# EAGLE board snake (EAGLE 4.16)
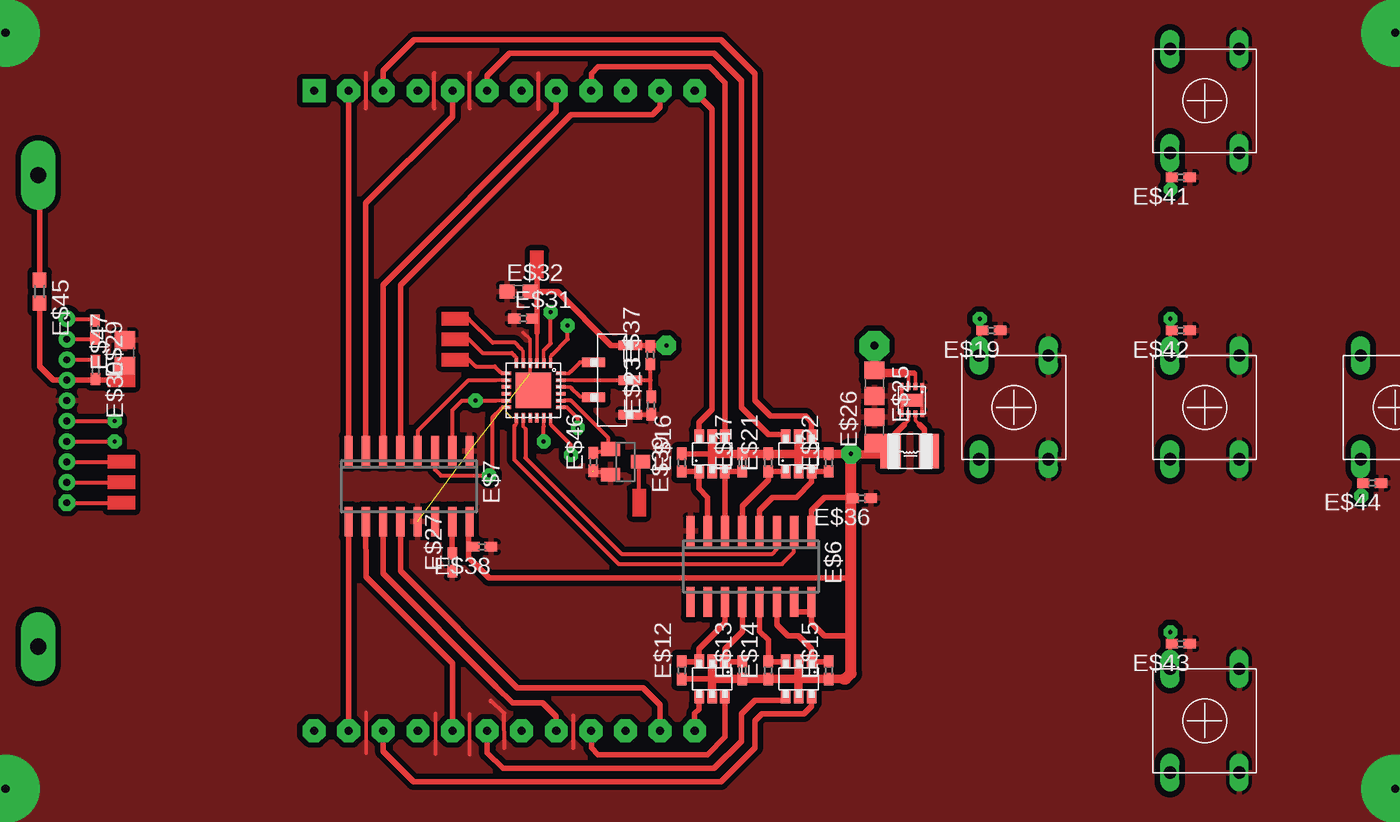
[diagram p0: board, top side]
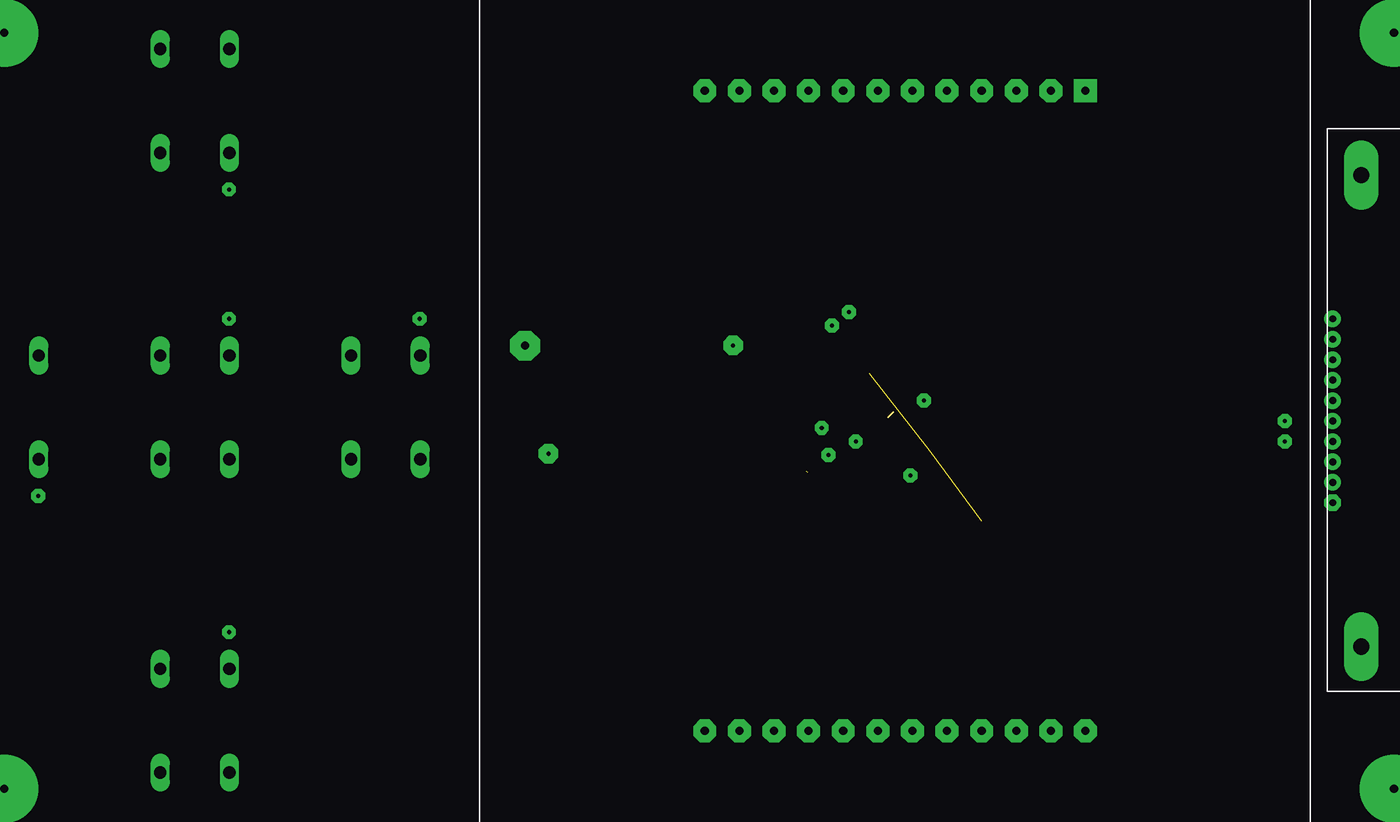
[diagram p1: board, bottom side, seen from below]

Size 0.4 x 0.4 mm. Coordinates in mm from the lower left corner, seen from the top.
Outline: 0.4,0 0,0.4
Copper layers (1*16): Top 0.035mm / dielectric 1.5mm / Bottom 0.035mm
Design rules "default": minimum track width 10mil, minimum drill 24mil, track to track 8mil, track to pad 8mil, pad to pad 8mil, via to via 8mil, smd to smd 8mil, copper to edge 40mil, drill to drill 8mil, minimum pad ring 10mil, minimum via ring 8mil, stop-mask expansion 4mil, vias tented up to drill 0mil, thermal gap 10mil

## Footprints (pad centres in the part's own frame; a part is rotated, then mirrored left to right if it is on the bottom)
LC2088AURYG1C = drill 0.6 pad 1.676 square: P$1 -13.97,-23.495 | drill 0.6 pad 1.676 octagon: P$2 -11.43,-23.495; P$3 -8.89,-23.495; P$4 -6.35,-23.495; P$5 -3.81,-23.495; P$6 -1.27,-23.495; P$7 1.27,-23.495; P$8 3.81,-23.495; P$9 6.35,-23.495; P$10 8.89,-23.495; P$11 11.43,-23.495; P$12 13.97,-23.495; P$13 -13.97,23.495; P$14 -11.43,23.495; P$15 -8.89,23.495; P$16 -6.35,23.495; P$17 -3.81,23.495; P$18 -1.27,23.495; P$19 1.27,23.495; P$20 3.81,23.495; P$21 6.35,23.495; P$22 8.89,23.495; P$23 11.43,23.495; P$24 13.97,23.495
SUPERSOT-6 = smd 0.7 x 1: P$1 -0.95,1.3; P$2 0,1.3; P$3 0.95,1.3; P$4 -0.95,-1.3; P$5 0,-1.3; P$6 0.95,-1.3
SO16 = smd 0.6 x 2.2: 1 -4.445,-2.6; 2 -3.175,-2.6; 3 -1.905,-2.6; 4 -0.635,-2.6; 5 0.635,-2.6; 6 1.905,-2.6; 7 3.175,-2.6; 8 4.445,-2.6; 9 4.445,2.6; 10 3.175,2.6; 11 1.905,2.6; 12 0.635,2.6; 13 -0.635,2.6; 14 -1.905,2.6; 15 -3.175,2.6; 16 -4.445,2.6
SW_TACT_KSL4 = drill 0.9 long: 1 -3.81,2.54; 2 -3.81,-2.54; 3 3.81,-2.54; 4 3.81,2.54
R0402 = smd 0.9 x 0.7: 1 -0.65,0; 2 0.65,0
C0402 = smd 0.9 x 0.7: 1 -0.65,0; 2 0.65,0
QFN24 = smd 0.7 x 0.25: 1 -2,1.25; 2 -2,0.75; 3 -2,0.25; 4 -2,-0.25; 5 -2,-0.75; 6 -2,-1.25; 13 2,-1.25; 14 2,-0.75; 15 2,-0.25; 16 2,0.25; 17 2,0.75; 18 2,1.25 | smd 0.25 x 0.7: 7 -1.25,-2; 8 -0.75,-2; 9 -0.25,-2; 10 0.25,-2; 11 0.75,-2; 12 1.25,-2; 19 1.25,2; 20 0.75,2; 21 0.25,2; 22 -0.25,2; 23 -0.75,2; 24 -1.25,2 | smd 2.6 x 2.6: EP 0,0
WSON8 = smd 0.28 x 0.5: 1 -1,-1; 2 -0.5,-1; 3 0,-1; 4 0.5,-1; 5 0.5,1; 6 0,1; 7 -0.5,1; 8 -1,1 | smd 1.6 x 0.9: EP -0.25,0
C0805 = smd 1.3 x 1.5: 1 -0.95,0; 2 0.95,0
LQH32C = smd 1.5 x 2.5: P$1 -1.4,0; P$2 1.4,0
C0603 = smd 1.1 x 1: 1 -0.85,0; 2 0.85,0
HEADER5S = smd 0.7 x 1.7: P$1 0,1.35; P$2 2.55,1.35; P$3 -2.55,1.35; P$4 -1.3,-1.35; P$5 1.25,-1.35
SOT23 = smd 1 x 1.4: 1 -0.95,-1.1; 2 0.95,-1.1; 3 0,1.1
R0603 = smd 1.1 x 1: 1 -0.85,0; 2 0.85,0
NHD-C0216-SPI = drill 0.5 pad 1.2 round: 1 0,0; 5 1.5,0; 6 3,0; 7 4.5,0; 8 6,0; 9 7.5,0; 10 9,0; 11 10.5,0; 12 12,0 | drill 0.5 pad 1.2 octagon: 13 13.5,0 | drill 1.2 pad 2.54 long: 18 24.05,2.1; 19 -10.55,2.1

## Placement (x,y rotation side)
E$1  [LC2088AURYG1C]  -0.14,0.5 180 bottom
E$2  [SUPERSOT-6]  not placed on the board
E$3  [SUPERSOT-6]  not placed on the board
E$4  [SUPERSOT-6]  not placed on the board
E$5  [SUPERSOT-6]  not placed on the board
E$6  [SO16]  not placed on the board
E$7  [SO16]  -7.13,-5.04 180 top
E$9  [SW_TACT_KSL4]  not placed on the board
E$10  [SW_TACT_KSL4]  not placed on the board
E$11  [SW_TACT_KSL4]  not placed on the board
E$12  [R0402]  not placed on the board
E$13  [R0402]  not placed on the board
E$14  [R0402]  not placed on the board
E$15  [R0402]  not placed on the board
E$16  [R0402]  not placed on the board
E$17  [R0402]  not placed on the board
E$18  [SW_TACT_KSL4]  not placed on the board
E$19  [C0402]  not placed on the board
E$20  [QFN24]  2,2 270 top
E$21  [R0402]  not placed on the board
E$22  [R0402]  not placed on the board
E$23  [R0402]  not placed on the board
E$24  [WSON8]  29.52,1.28 180 top  (outside the outline)
E$25  [C0805]  not placed on the board
E$26  [C0805]  not placed on the board
E$27  [C0402]  not placed on the board
E$28  [LQH32C]  not placed on the board
E$29  [R0402]  not placed on the board
E$30  [R0402]  not placed on the board
E$31  [R0402]  not placed on the board
E$32  [C0603]  not placed on the board
E$35  [HEADER5S]  not placed on the board
E$36  [R0402]  not placed on the board
E$37  [R0402]  not placed on the board
E$38  10K  [C0402]  not placed on the board
E$39  [SOT23]  not placed on the board
E$40  [SW_TACT_KSL4]  not placed on the board
E$41  [C0402]  not placed on the board
E$42  [C0402]  not placed on the board
E$43  [C0402]  not placed on the board
E$44  [C0402]  not placed on the board
E$45  [R0603]  not placed on the board
E$46  [R0402]  not placed on the board
E$47  [C0805]  not placed on the board
E$48  [NHD-C0216-SPI]  not placed on the board

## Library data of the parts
E$1 = display-hp
E$2-E$5 E$9-E$11 E$18 E$28 E$35 E$40 = sb
E$6 E$7 E$12-E$17 E$19 E$21-E$23 E$25 E$26 E$29-E$32 E$36 E$37 E$39 E$41-E$47 = ref-packages
E$20 = freescale
E$24 = texas
E$27 E$38 = rcl
E$48 = display-lcd

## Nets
GND: E$6.8 E$7.1 E$7.13 E$9.2 E$9.3 E$10.2 E$10.3 E$11.2 E$11.3 E$18.2 E$18.3 E$19.1 E$23.1 E$24.1 E$24.4 E$24.5 E$24.8 E$24.EP E$25.2 E$26.2 E$27.1 E$31.1 E$32.1 E$35.P$2 E$36.1 E$38.1 E$39.2 E$40.2 E$40.3 E$41.1 E$42.1 E$43.1 E$44.1 E$46.1 E$47.2 E$48.8
S$2: E$24.2 E$24.3
S$3: E$24.7
S$20: E$24.6

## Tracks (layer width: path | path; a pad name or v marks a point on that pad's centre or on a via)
GND  (via drill 0.6 pad 5)  (3 unrouted)
  Top 0.254: 29.02,1.28 E$24.4 | E$24.5 29.02,1.28 | 30.52,1.28 E$24.1 | 29.02,1.28 30.52,1.28 | 30.52,1.28 E$24.8 | -2.7,-24.75 -2.7,-21.75 | -5.2,-24.7 -5.2,-21.7 | -10.3,-24.65 -10.3,-21.65 | 1.25,6.25 1.75,5.75 1.75,3.25
  Top 0.305: 2.36,22.66 2.36,25.27 | -2.69,22.71 -2.69,25.31 | -5.29,22.71 -5.29,25.31 | 4.93,-24.27 4.93,-21.88 | -1.14,-20.84 -1.14,-20.76 -0.15,-21.7 -0.14,-24.27 | -10.29,22.71 -10.29,25.31 | 10.75,0.2 9.75,0.2 | 6.3,-4 7.3,-4
  other vias: -36.75,28.25 65.25,28.25 -36.75,-27.25 65.25,-27.25
  pour Top (isolate 0.406): 69.75,-30.93 -56.6,-30.93 -56.6,31.93 69.75,31.93
S$1
  Top 0.406: -9.05,24.05 -9.05,25.45 -6.75,27.75 15.75,27.75 18.25,25.25 18.25,1.25 19.4,0.1 22,0.1 22.4,-0.35 22.4,-1.3
S$2
  Top 0.254: E$24.3 29.52,3.28 | E$24.2 30.02,3.28 29.92,3.28
  Top 0.406: 29.52,3.28 29.92,3.28
S$3
  Top 0.254: E$24.7 30.02,-0.22 30.32,-0.52
  Top 0.406: 30.32,-0.52 30.67,-0.87 30.67,-1.72
S$4
  Top 0.406: 16.05,-1.25 16.05,24.6 14.9,25.75 6.75,25.75 6.25,25.25 6.25,24.05
S$5
  Top 0.406: 16.05,-14.74 16.05,-15.06 14.15,-16.96 14.15,-17.91 13.67,-17.91 12.88,-17.91
S$6
  Top 0.406: -10.31,-7.58 -10.3,-11.7 -3.95,-18.04 -3.95,-22.99
S$7
  Top 0.406: 17.32,-13.47 17.32,-15.69 16.05,-16.96 16.05,-17.91 17.32,-17.91
S$8
  Top 0.406: 18.59,-13.47 18.59,-15.69 19.23,-16.33 19.23,-17.91 20.5,-17.91
S$9
  Top 0.406: 19.86,-13.47 19.86,-15.22 20.66,-16.01 21.45,-16.01 22.4,-16.96 22.4,-17.91 23.67,-17.91
S$10
  Top 0.406: 14.78,-7.12 14.78,-5.85 14.15,-5.21 14.15,-3.95 12.88,-3.95
S$11
  Top 0.406: 16.05,-7.12 16.05,-3.95 17.32,-3.95
S$12
  Top 0.406: 17.32,-7.12 17.32,-6.48 19.23,-4.58 19.23,-3.95 20.18,-3.95 20.5,-3.95
S$13
  Top 0.406: 18.59,-7.75 18.59,-6.8 19.55,-5.85 21.29,-5.85 22.4,-4.74 22.4,-3.95 | 22.4,-3.95 22.56,-3.95 | 22.4,-3.95 23.67,-3.95
S$14
  Top 0.406: 12.88,-19.19 15.1,-19.19
  Top 0.61: 15.1,-20.45 15.1,-19.19 15.1,-17.91
S$15
  Top 0.61: 21.45,-20.45 21.45,-17.91
S$16
  Top 0.305: -32.1,-6.25 -28.75,-6.25
S$17
  Top 0.406: 21.25,-14.25 22.25,-14.25
S$18
  Top 0.406: 12.88,-2.68 15.1,-2.68
  Top 0.61: 15.1,-3.95 15.1,-2.68 15.1,-1.41
S$19
  Top 0.61: 21.45,-3.95 21.45,-1.41
S$20
  Top 0.254: E$24.6 29.52,-0.22 29.22,-0.52
  Top 0.406: 28.52,-1.22 29.22,-0.52
S$21
  Top 0.254: 1.4,-0.8 1.25,-0.65 1.25,-0.25
  Top 0.305: 19.85,-8.65 19.85,-9.65 19.55,-10 8.45,-10 1.4,-2.95 1.4,-0.8
S$22
  Top 0.254: 0.65,-0.55 0.75,-0.45 0.75,-0.25
  Top 0.305: 21.1,-8.35 21.1,-9.85 20.25,-10.75 8.25,-10.75 0.6,-3.1 0.6,-0.6 0.65,-0.55
S$23
  Top 0.406: 20.25,-1.25 19.25,-1.25 17.25,0.75 17.25,24.75 15.25,26.75 0.25,26.75 -1.4,25.1 -1.4,24.1
S$24
  Top 0.406: 6.25,-23 6.25,-24.25 6.75,-24.75 14.75,-24.75 16.05,-23.45 16.05,-20.9
S$25
  Top 0.406: 14.15,-1.25 14.15,-0.35 15.1,0.6 15.1,22.65 13.75,24
S$26
  Top 0.406: -9.05,-23 -9.05,-24.5 -6.8,-26.75 15.75,-26.75 18.25,-24.25 18.25,-22.25 18.75,-21.75 21.85,-21.75 22.4,-21.2 22.4,-20.2
S$27  (via drill 0.6 pad 2.18)
  Top 0.61: v27.02,5.28 27.02,3.28 29.27,3.28
S$28
  Top 0.61: 25.52,-2.72 28.12,-2.72
S$29
  Top 0.406: -1.4,-23.1 -1.4,-24.6 -0.25,-25.75 15.25,-25.75 17.25,-23.75 17.25,-21.75 18.25,-20.75 20.25,-20.75
S$30
  Top 0.406: 13.83,-22.99 13.83,-21.73 14.15,-21.41 14.15,-20.45
S$31
  Top 0.406: -2.75,-8.25 -2.75,-10.25 -1.25,-11.75 25.25,-11.75
S$32
  Top 0.254: -0.75,1.25 -0.25,1.25
  Top 0.305: -0.75,1.25 -3.25,1.25 -3.95,0.55 -3.95,-1.95
S$33
  Top 0.254: 4.7,3.35 4.6,3.25 4.3,3.25
  Top 0.305: 4.7,3.35 5.4,4.05 6.55,4.05
S$34
  Top 0.254: -0.75,2.75 0.15,2.75
  Top 0.305: -0.75,2.75 -2.75,2.75 -6.5,-1 -6.5,-2
S$35
  Top 0.305: -31.75,4.25 -30.25,4.25
S$36
  Top 0.305: -31.75,5.75 -30.25,5.75
S$37
  Top 0.305: -31.75,7.25 -30.25,7.25
S$38
  Top 0.305: 4.25,1.25 4.75,1.25 7.45,-1.45 7.45,-2.45
S$39
  Top 0.305: 9.75,-5.75 9.75,-3.25
S$40  (via drill 0.3 pad 1.02)
  Top 0.305: 4.25,0.75 4.45,0.75 5.25,-0.05 v5.25,-0.75
S$41  (via drill 0.3 pad 1.42)
  Top 0.254: 2.25,4.25 2.25,6.25
  Top 0.406: 2.25,6.25 2.25,9.25 | 2.25,9.25 3.75,9.25 7.7,5.3 v11.75,5.3 | 2.25,9.25 2.25,11.25
S$42
  Top 0.406: -28.75,2.75 -33.25,2.75 -34.25,3.75 -34.25,8.25
S$43
  Top 0.305: 34.75,4.75 34.75,7.2
S$44
  Top 0.406: 25.3,-5.85 23.36,-5.85 22.4,-6.8 22.4,-7.75
S$45
  Top 0.406: 25.3,-16.01 23.36,-16.01 22.4,-15.06 22.4,-14.11
S$46  (via drill 0.3 pad 1.02)
  other vias: -2.25,1.25
S$47
  Top 0.406: -34.25,10.25 -34.25,17.85
S$48
  Top 0.254: 0.75,4.3 0.75,4.4 0.6,4.55
  Top 0.305: 0.6,4.55 0.4,4.75 -1.75,4.75 -2.75,5.75 -3.25,5.75
S$49
  Top 0.254: 1.25,4.25 1.25,4.9 1.1,5.05
  Top 0.305: -3.25,7.25 -2.75,7.25 -1,5.5 0.65,5.5 1.1,5.05
S$51  (via drill 0.3 pad 1.02)
  Top 0.305: -32.1,-1.75 v-28.75,-1.75
S$52  (via drill 0.3 pad 1.02)
  Top 0.305: -32.15,-0.25 v-28.75,-0.25
S$53
  Top 0.254: 5,2.75 4.3,2.75
  Top 0.305: 5,2.75 10.6,2.75
S$54
  Top 0.254: 4.8,2.15 4.7,2.25 4.3,2.25
  Top 0.305: 4.8,2.15 5.4,1.55 5.95,1.55
S$55
  Top 0.305: 10.6,1.75 10.6,3.75
S$56  (via drill 0.3 pad 1.02)
  Top 0.254: 3.35,-0.6 3.25,-0.5 3.25,-0.25
  Top 0.305: 3.35,-0.6 4.75,-2 v4.75,-2.75
S$57
  Top 0.254: 2.75,4.25 2.75,4.95 2.85,5.05
  Top 0.305: 2.85,5.05 3.25,5.45 3.25,7.75
S$58
  Top 0.254: 3.35,4.6 3.25,4.5 3.25,4.25
  Top 0.305: 4.5,6.75 4.5,5.75 3.35,4.6
S$59  (via drill 0.3 pad 1.02)
  other vias: 4.5,6.75
S$60  (via drill 0.3 pad 1.02)
  other vias: 3.25,7.75
S$61
  Top 0.61: 15.1,-19.19 24.76,-19.19 | 25.3,-2.68 | 25.3,-2.68 24.76,-2.68 15.1,-2.68
  Top 0.813: 24.76,-19.19 24.89,-19.19 25.3,-18.78 25.3,-2.68
S$62  (via drill 0.3 pad 1.02)
  Top 0.305: 48.75,-18.25 v48.75,-15.75
S$63  (via drill 0.3 pad 1.02)
  Top 0.254: 2.75,-0.65 2.75,-0.25
  Top 0.305: v2.75,-1.75 2.75,-0.65
S$64  (via drill 0.3 pad 1.02)
  other vias: 34.75,7.25
S$65  (via drill 0.3 pad 1.42)
  other vias: 25.3,-2.65
S$66  (via drill 0.3 pad 1.02)
  Top 0.305: v48.75,16.75 48.75,19.25
S$67  (via drill 0.3 pad 1.02)
  Top 0.305: 48.75,4.75 v48.75,7.25
S$68  (via drill 0.3 pad 1.02)
  Top 0.305: v62.75,-5.75 62.75,-3.25
S$70
  Top 0.305: 6.25,-2.5 7.25,-2.5
S$71
  Top 0.305: -32.1,-4.75 -28.75,-4.75
S$72
  Top 0.305: -32.1,-3.25 -28.75,-3.25
S$73
  Top 0.406: 11.29,23.99 11.29,22.77 11.22,22.73 10.75,22.25 4.75,22.25 -7.77,9.72 -7.77,-2.5
S$74
  Top 0.254: 0,3.25 -0.35,3.25 -0.45,3.35
  Top 0.305: -0.45,3.35 -0.85,3.75 -2.25,3.75 -2.75,4.25 -3.25,4.25
S$75
  Top 0.406: 3.67,23.99 3.67,22.44 -9.04,9.73 -9.04,-1.23
S$76  (via drill 0.3 pad 1.02)
  other vias: -1.25,-4.25
S$77
  Top 0.406: -10.31,-1.23 -10.31,15.73 -3.95,22.09 -3.95,23.99
S$79
  Top 0.406: -11.58,-2.5 -11.58,24.15
S$81
  Top 0.406: -7.77,-7.9 -7.77,-11.26 0.79,-19.82 10.02,-19.82 11.29,-21.09 11.29,-22.99
S$83
  Top 0.406: -9.04,-8.06 -9.04,-11.45 -0.75,-19.75 0.45,-20.95 2.67,-20.95 3.67,-21.91 3.67,-22.68 3.67,-22.99 | 3.67,-22.99
S$87
  Top 0.406: -11.58,-8.85 -11.58,-10.43 -11.57,-14.97 -11.57,-22.99
S$93
  Top 0.254: -0.4,0.65 -0.3,0.75 0.01,0.75
  Top 0.305: -5.23,-2.5 -5.23,-3.82 -4.8,-4.25 -1.25,-4.25 -1,-4 -1,0.05 -0.4,0.65
S$95
  Top 0.406: -3.96,-9.67 -3.96,-7.58
(copper drawn outside any net)
  shapes: Top area x9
